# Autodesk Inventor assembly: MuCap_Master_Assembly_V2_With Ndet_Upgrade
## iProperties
Shininess: 64.0
Length Units: 11269
Angle Units: 11279
Time Units: 11290
Mass Units: 11283
Length Display Precision: 3
Angle Display Precision: 2
Compacted: True
Created: 2004-08
Part Number: MuCap_Master_Assembly_V2_With Ndet_Upgrade
Document SubType Name: Assembly
Designer: John Blackburn
Manufacturer: Standard
Standards Organization: Custom
Density: 0.0
Volumn: 0.0
Area: 0.0
PropertySet Name: Model Information
Control State: 0
Master: False
Checked Out: False
Author: John Blackburn
